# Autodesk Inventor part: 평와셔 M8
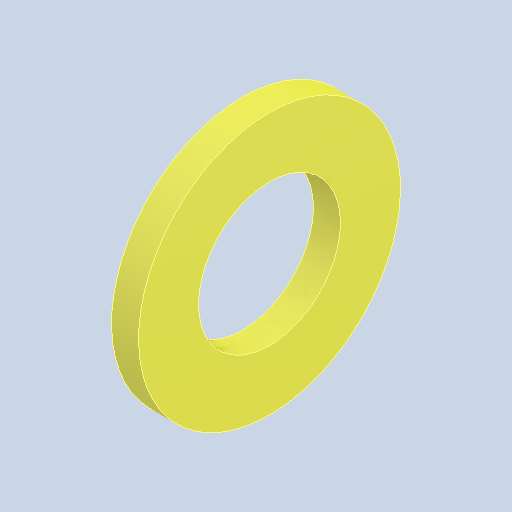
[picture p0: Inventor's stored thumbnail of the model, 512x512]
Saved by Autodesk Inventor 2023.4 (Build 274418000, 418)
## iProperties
Created: 2024-04
Part Number: 평와셔 M8
Material: 강철, 연강
Description: 평면 와셔
Document SubType Name: Modeling
Designer: EDU
Density: 7.86 g/cm^3
Appearance: 기본값
Author: jhkim
Sending System: Autodesk Inventor 2025
Preprocessor: ST-DEVELOPER v20
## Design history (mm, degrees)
node "평와셔 M81"
node "솔리드1"
body "Solid1"
